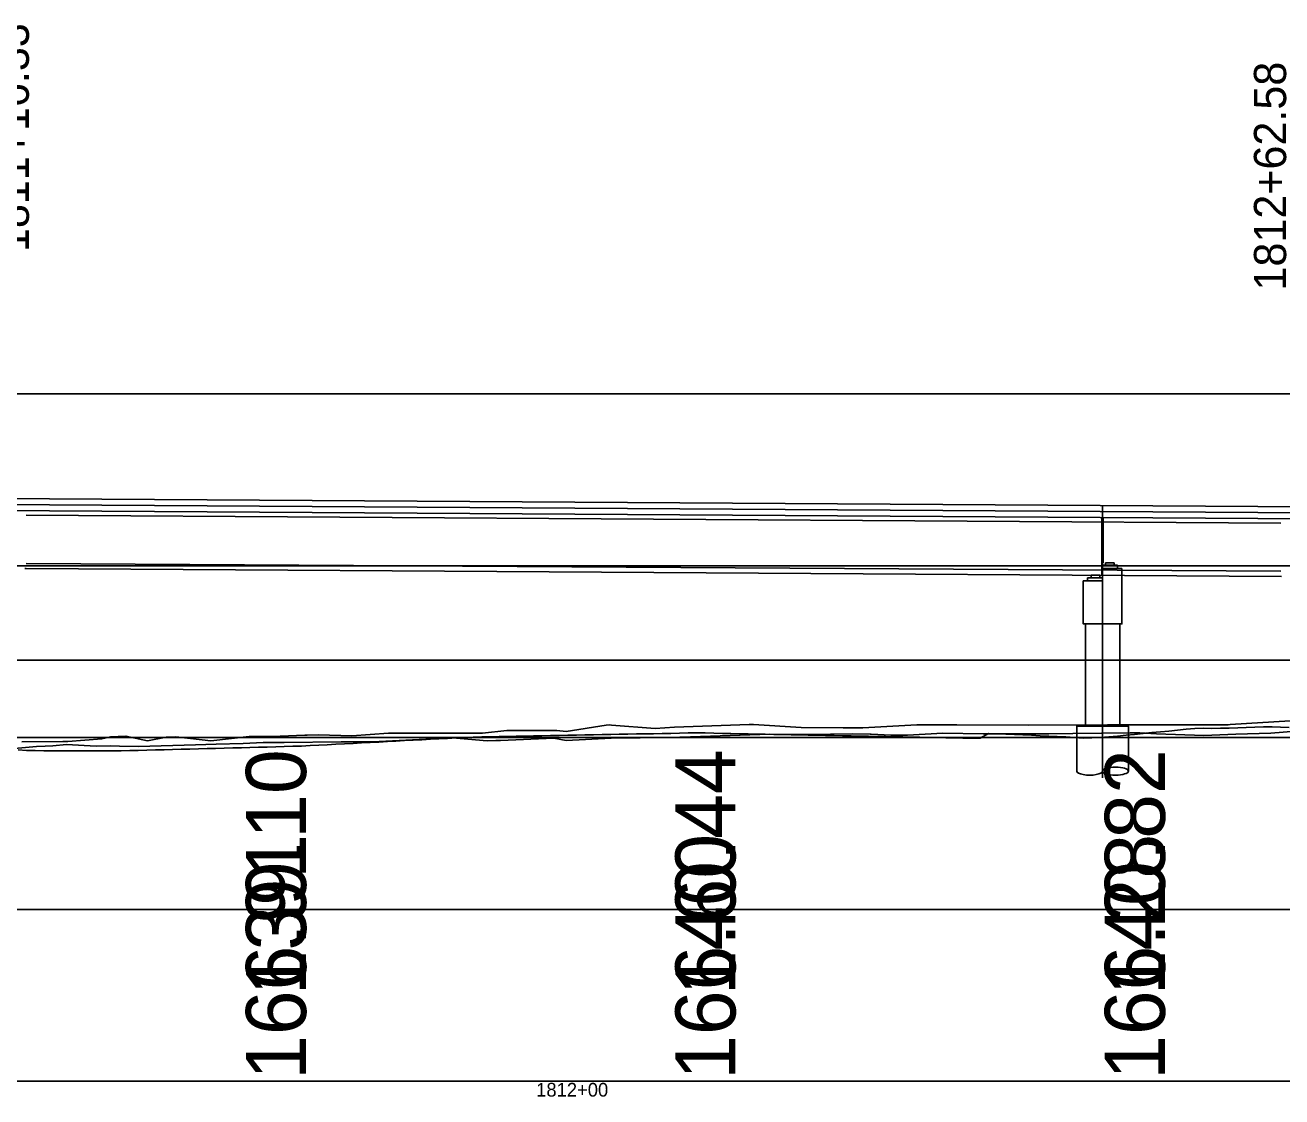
# Model space of a CAD drawing. Extents: x 2126510 to 2136144, y 865066 to 868066.
# Drawn here: x 2133739.3 to 2133885.6, y 867812.5 to 867937.3 of the extents above; entities that cross this region are included whole.
import ezdxf

# ---------------------------------------------------------------- set-up
doc = ezdxf.new("R2010")
doc.units = 0
for name, color, linetype in [('RD_DTM_BkLn1', 7, 'Continuous'), ('RD_EX_Bldg', 7, 'Continuous'), ('RD_EX_Bridge', 7, 'Continuous'), ('RD_EX_Conc_Curb', 7, 'Continuous'), ('RD_EX_GuardRail', 7, 'Continuous'), ('RD_EX_H2O', 7, 'Continuous'), ('RD_EX_Misc', 7, 'Continuous'), ('RD_EX_Misc_Golf_Cartpath', 7, 'Continuous'), ('RD_EX_UT', 7, 'Continuous'), ('RD_HC_Data', 7, 'Continuous'), ('RD_HC_txCode', 7, 'Continuous')]:
    doc.layers.add(name, color=color, linetype=linetype)

msp = doc.modelspace()

# ---------------------------------------------------------------- linework, layer by layer
at = {"layer": 'RD_DTM_BkLn1'}
for p, q in [((2133649.16, 867881.28), (2134230.74, 867877.62)), ((2133864.74, 867874.38), (2133866.49, 867874.38)), ((2133864.74, 867874.38), (2133864.74, 867874.01)), ((2133864.74, 867872.55), (2133864.74, 867874.01)), ((2133866.99, 867874.01), (2133864.74, 867874.01)), ((2133866.49, 867874.38), (2133866.49, 867874.01)), ((2133864.74, 867872.92), (2133862.99, 867872.92)), ((2133862.99, 867872.92), (2133862.99, 867872.55)), ((2133862.74, 867867.55), (2133862.74, 867855.65)), ((2133866.74, 867867.55), (2133866.74, 867855.65))]:
    msp.add_line(p, q, dxfattribs=at)
for points in [[(2133866.99, 867874.01), (2133866.99, 867867.55), (2133862.49, 867867.55), (2133862.49, 867872.55), (2133864.74, 867872.55)], [(2133861.74, 867850.41), (2133861.74, 867855.65), (2133867.74, 867855.65), (2133867.74, 867850.41)]]:
    msp.add_lwpolyline(points, dxfattribs=at)
msp.add_ellipse((2133863.24, 867850.41), major_axis=(-1.5, 0), ratio=0.310397, start_param=0, end_param=3.141593, dxfattribs=at)
msp.add_ellipse((2133866.24, 867850.41), major_axis=(-1.5, 0), ratio=0.310397, dxfattribs=at)
at = {"layer": 'RD_EX_Bldg'}
for p, q in [((2133866.07, 867874.38), (2133864.74, 867874.38)), ((2133863.4, 867872.92), (2133864.74, 867872.92))]:
    msp.add_line(p, q, dxfattribs=at)
at = {"layer": 'RD_EX_Bridge'}
for p, q in [((2133865.07, 867874.67), (2133866.07, 867874.67)), ((2133865.07, 867874.38), (2133865.07, 867874.67)), ((2133866.07, 867874.67), (2133866.07, 867874.38)), ((2133864.4, 867873.22), (2133863.4, 867873.22)), ((2133863.4, 867873.22), (2133863.4, 867872.92)), ((2133864.4, 867873.22), (2133864.4, 867872.92))]:
    msp.add_line(p, q, dxfattribs=at)
at = {"layer": 'RD_EX_Conc_Curb'}
msp.add_lwpolyline([(2133735.45, 867852.81), (2133740.63, 867853.26), (2133741.64, 867853.32), (2133742.52, 867853.36), (2133744.12, 867853.52), (2133747.56, 867853.32), (2133749.21, 867853.35), (2133750.27, 867853.32), (2133752.48, 867853.26), (2133759.12, 867853.48), (2133761.55, 867853.55), (2133764.69, 867853.64), (2133767, 867853.73), (2133769.47, 867853.74), (2133776.07, 867853.81), (2133776.46, 867853.82), (2133776.77, 867853.82), (2133779.12, 867853.81), (2133779.65, 867853.81), (2133779.71, 867853.81), (2133779.74, 867853.81), (2133789.05, 867854.3), (2133793.09, 867853.95), (2133794.08, 867853.96), (2133794.63, 867853.97), (2133800.84, 867854.23), (2133802.3, 867853.99), (2133807.54, 867854.25), (2133814.29, 867854.34), (2133816.76, 867854.41), (2133825.98, 867854.7), (2133830.48, 867854.66), (2133835.58, 867854.74), (2133837.68, 867854.7), (2133837.8, 867854.7), (2133840.1, 867854.59), (2133842.01, 867854.59), (2133846.13, 867854.82), (2133850.82, 867854.75), (2133858.48, 867854.74), (2133861.29, 867854.81), (2133867.94, 867854.86), (2133869.06, 867854.87), (2133871, 867854.77), (2133876.51, 867854.56), (2133880.26, 867854.72), (2133884.33, 867854.82), (2133889.12, 867855.2)], dxfattribs=at)
at = {"layer": 'RD_EX_GuardRail'}
for p, q in [((2135251.98, 867894.32), (2130671.73, 867894.32)), ((2135251.98, 867874.32), (2133154.4, 867874.32)), ((2135251.98, 867854.32), (2130671.73, 867854.32)), ((2135251.98, 867834.32), (2130671.73, 867834.32)), ((2135251.98, 867814.32), (2130671.73, 867814.32))]:
    msp.add_line(p, q, dxfattribs=at)
at = {"layer": 'RD_EX_H2O'}
for points in [[(2133786.47, 867854.12), (2133787.47, 867854.17), (2133788.47, 867854.22), (2133789.47, 867854.27), (2133790.47, 867854.32), (2133791.47, 867854.38), (2133792.47, 867854.4), (2133793.47, 867854.42), (2133794.47, 867854.44), (2133795.47, 867854.46), (2133796.47, 867854.48), (2133797.47, 867854.5), (2133798.47, 867854.51), (2133799.47, 867854.53), (2133800.47, 867854.55), (2133801.47, 867854.57), (2133802.47, 867854.59), (2133803.47, 867854.61), (2133804.47, 867854.63), (2133805.47, 867854.64), (2133806.47, 867854.66), (2133807.47, 867854.68), (2133808.47, 867854.7), (2133809.47, 867854.72), (2133810.47, 867854.74), (2133811.47, 867854.76), (2133812.47, 867854.77), (2133813.47, 867854.79), (2133814.47, 867854.81), (2133815.47, 867854.83), (2133816.47, 867854.86), (2133817.47, 867854.88), (2133818.47, 867854.86), (2133819.47, 867854.82), (2133820.47, 867854.8), (2133821.47, 867854.78), (2133822.47, 867854.76), (2133823.47, 867854.74), (2133824.47, 867854.72), (2133825.47, 867854.71), (2133826.47, 867854.69), (2133827.47, 867854.67), (2133828.47, 867854.65), (2133829.47, 867854.63), (2133830.47, 867854.61), (2133831.47, 867854.59), (2133832.47, 867854.57), (2133833.47, 867854.55), (2133834.47, 867854.53), (2133835.47, 867854.51), (2133836.47, 867854.49), (2133837.47, 867854.47), (2133838.47, 867854.45), (2133839.47, 867854.43), (2133840.47, 867854.41), (2133841.47, 867854.39), (2133842.47, 867854.37), (2133843.47, 867854.35), (2133844.47, 867854.33), (2133845.47, 867854.31), (2133846.47, 867854.29), (2133847.47, 867854.27), (2133848.47, 867854.25), (2133849.47, 867854.23), (2133850.47, 867854.26), (2133851.47, 867854.81), (2133852.47, 867854.77), (2133853.47, 867854.72), (2133854.47, 867854.67), (2133855.47, 867854.63), (2133856.47, 867854.58), (2133857.47, 867854.53), (2133858.47, 867854.49), (2133859.47, 867854.44), (2133860.47, 867854.39), (2133861.47, 867854.31), (2133862.47, 867854.23), (2133863.47, 867854.27), (2133864.47, 867854.33), (2133865.47, 867854.39), (2133866.47, 867854.49), (2133867.47, 867854.59), (2133868.47, 867854.69), (2133869.47, 867854.79), (2133870.47, 867854.89), (2133871.47, 867854.98), (2133872.47, 867855.08), (2133873.47, 867855.18), (2133874.47, 867855.28), (2133875.47, 867855.38), (2133876.47, 867855.41), (2133877.47, 867855.38), (2133878.47, 867855.42), (2133879.47, 867855.43), (2133880.47, 867855.46), (2133881.47, 867855.5), (2133882.47, 867855.54), (2133883.47, 867855.58), (2133884.47, 867855.55), (2133885.47, 867855.53), (2133886.47, 867855.5)], [(2133738.47, 867852.88), (2133739.47, 867852.83), (2133740.47, 867852.8), (2133741.47, 867852.79), (2133742.47, 867852.79), (2133743.47, 867852.79), (2133744.47, 867852.77), (2133745.47, 867852.76), (2133746.47, 867852.78), (2133747.47, 867852.78), (2133748.47, 867852.78), (2133749.47, 867852.78), (2133750.47, 867852.78), (2133751.47, 867852.8), (2133752.47, 867852.83), (2133753.47, 867852.85), (2133754.47, 867852.88), (2133755.47, 867852.9), (2133756.47, 867852.93), (2133757.47, 867852.95), (2133758.47, 867852.98), (2133759.47, 867853.01), (2133760.47, 867853.03), (2133761.47, 867853.06), (2133762.47, 867853.08), (2133763.47, 867853.11), (2133764.47, 867853.14), (2133765.47, 867853.16), (2133766.47, 867853.19), (2133767.47, 867853.21), (2133768.47, 867853.24), (2133769.47, 867853.26), (2133770.47, 867853.31), (2133771.47, 867853.33), (2133772.47, 867853.38), (2133773.47, 867853.44), (2133774.47, 867853.49), (2133775.47, 867853.54), (2133776.47, 867853.59), (2133777.47, 867853.64), (2133778.47, 867853.7), (2133779.47, 867853.75), (2133780.47, 867853.8), (2133781.47, 867853.85), (2133782.47, 867853.91), (2133783.47, 867853.96), (2133784.47, 867854.01), (2133785.47, 867854.06), (2133786.47, 867854.12)]]:
    msp.add_lwpolyline(points, dxfattribs=at)
at = {"layer": 'RD_EX_Misc'}
for p, q in [((2133649.16, 867882.7), (2134667.76, 867876.29)), ((2131523, 867814.32), (2135677.25, 867814.32))]:
    msp.add_line(p, q, dxfattribs=at)
msp.add_lwpolyline([(2131430.13, 867814.32), (2131430.13, 867863.32), (2136143.96, 867863.32)], dxfattribs=at)
at = {"layer": 'RD_EX_Misc_Golf_Cartpath'}
msp.add_lwpolyline([(2133738.91, 867853.82), (2133743.7, 867853.86), (2133744.26, 867853.86), (2133748.22, 867854.16), (2133749.22, 867854.39), (2133751.02, 867854.49), (2133753.53, 867853.95), (2133755.72, 867854.35), (2133756.82, 867854.41), (2133759.89, 867854.04), (2133760.93, 867853.95), (2133765.36, 867854.46), (2133769, 867854.49), (2133771.87, 867854.61), (2133772.14, 867854.61), (2133773.46, 867854.65), (2133777.34, 867854.53), (2133781.6, 867854.83), (2133782.45, 867854.83), (2133784.44, 867854.85), (2133787.08, 867854.83), (2133787.15, 867854.83), (2133792.54, 867854.84), (2133795.37, 867855.13), (2133801.19, 867855.14), (2133802.29, 867855.03), (2133806.93, 867855.77), (2133807.3, 867855.8), (2133807.57, 867855.78), (2133812.64, 867855.36), (2133814.88, 867855.53), (2133823.59, 867855.85), (2133824.11, 867855.84), (2133829.63, 867855.5), (2133834.53, 867855.46), (2133836.84, 867855.46), (2133843.11, 867855.82), (2133843.88, 867855.82), (2133845.36, 867855.81), (2133847.78, 867855.81), (2133856.13, 867855.75), (2133865.33, 867855.79), (2133866.99, 867855.8), (2133878.39, 867855.82), (2133879.37, 867855.82), (2133879.58, 867855.83), (2133886.56, 867856.27)], dxfattribs=at)
at = {"layer": 'RD_EX_UT'}
msp.add_line((2133649.16, 867882.01), (2134667.76, 867875.59), dxfattribs=at)
at = {"layer": 'RD_HC_Data'}
for p, q in [((2133864.74, 867881.35), (2133864.74, 867849.65)), ((2133739.24, 867874.01), (2133739.4, 867874.01))]:
    msp.add_line(p, q, dxfattribs=at)
at = {"layer": 'RD_HC_txCode'}
for p, q in [((2133739.4, 867880.21), (2133885.49, 867879.29)), ((2133864.65, 867879.92), (2133864.65, 867873.22)), ((2133864.82, 867879.92), (2133864.82, 867874.67)), ((2133739.4, 867874.59), (2133885.49, 867873.67)), ((2133739.4, 867874.01), (2133885.57, 867873.08))]:
    msp.add_line(p, q, dxfattribs=at)

# ---------------------------------------------------------------- texts
at = {"layer": 'RD_EX_Misc'}
for s, height, p in [('1811+16.33', 3.75, (2133739.73, 867910.84)), ('1812+62.58', 3.75, (2133886.11, 867906.36)), ('139.10', 7, (2133772, 867824.32)), ('140.44', 7, (2133822, 867824.32)), ('140.82', 7, (2133872, 867824.32)), ('166.91', 7, (2133772, 867814.47)), ('166.60', 7, (2133822, 867814.47)), ('166.28', 7, (2133872, 867814.47))]:
    msp.add_text(s, height=height, rotation=90, dxfattribs=at).set_placement(p)
msp.add_text('1812+00', height=1.6, dxfattribs=at).set_placement((2133798.79, 867812.52))

doc.saveas('drawing.dxf')
